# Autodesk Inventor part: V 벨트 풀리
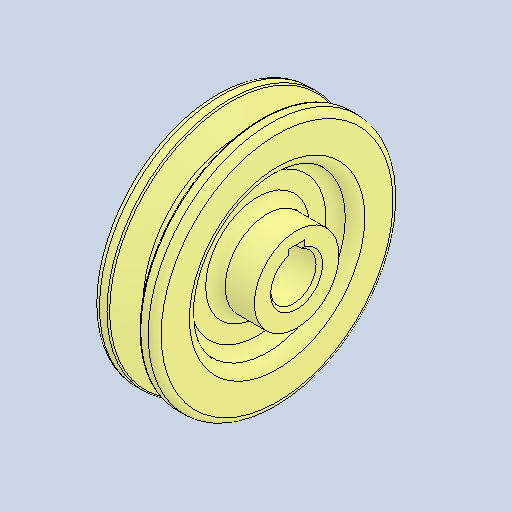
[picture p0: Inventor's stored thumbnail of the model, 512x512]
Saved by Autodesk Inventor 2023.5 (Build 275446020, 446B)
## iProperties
Created: 2026-07
Part Number: V 벨트 풀리
Material: 강철, 주조
Document SubType Name: Modeling
Designer: 1강의실14
Density: 7.85 g/cm^3
Appearance: 기본값
Author: jhkim
Sending System: Autodesk Inventor 2027
Preprocessor: ST-DEVELOPER v20.1
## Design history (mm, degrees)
node "V 벨트 풀리1"
node "솔리드2"
node "솔리드1"
